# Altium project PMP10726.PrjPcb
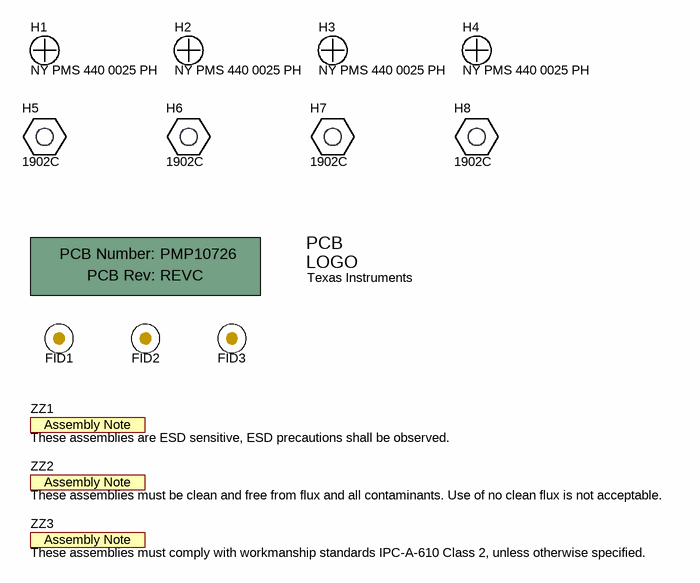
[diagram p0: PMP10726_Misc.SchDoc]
TID: PMP10726; TechSupport: http://www.ti.com/support; SCH_Rev: E3; PRJ_Title: 50W Buck-Boost; PRJ_Number: PMP10726; PRJ_Engineer: J Doong; PRJ_Customer: Public Release; PCB_Rev: REVC; PCB_Layout: J Doong; EVM_Orderable: N/A; CopyrightYear: 2016
2 sheets, 90 parts. Net scope: global (net labels, ports and power ports of the same name join across sheets).
Board file: PMP10726_TID.PcbDoc
Sheets:
  PMP10726_Misc.SchDoc
  PMP10726_Power.SchDoc

## Sheet PMP10726_Misc.SchDoc
size 431 x 279 mm; Date: Not shown in title block; ApprovedBy: Not shown in title block; CheckedBy: Not shown in title block; Author: Not shown in title block; CompanyName: Not shown in title block; Engineer: Not shown in title block; Organization: Not shown in title block; Address1: Not shown in title block; Address2: Not shown in title block; Address3: Not shown in title block; Address4: Not shown in title block; DocumentNumber: 2; Revision: Use project parameter SCH_Rev; SheetNumber: 2; SheetTotal: 2; PageSetup: Record=PageOptions¦CenterHorizontal=True¦CenterVertical=True¦PrintScale=1.00¦XCorrection=1.00¦YCorrection=1.00¦PrintKind=0¦BorderSize=5000000¦LeftOffset=0¦BottomOffset=0¦Orientation=2¦PaperLength=1000¦PaperWidth=1000¦Scale=100¦PaperSource=15¦PrintQuality=600¦MediaType=1¦DitherType=10¦PaperKind=Letter¦PrintScaleMode=1

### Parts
!PCB1  Printed Circuit Board  (value not drawn)  (mechanical)
FID1  Fiducial  [Fiducial10-20]  (value not drawn)
FID2  Fiducial  [Fiducial10-20]  (value not drawn)
FID3  Fiducial  [Fiducial10-20]  (value not drawn)
H1  NY PMS 440 0025 PH  [NY PMS 440 0025 PH]
H2  NY PMS 440 0025 PH  [NY PMS 440 0025 PH]
H3  NY PMS 440 0025 PH  [NY PMS 440 0025 PH]
H4  NY PMS 440 0025 PH  [NY PMS 440 0025 PH]
H5  1902C  [Keystone_1902C]
H6  1902C  [Keystone_1902C]
H7  1902C  [Keystone_1902C]
H8  1902C  [Keystone_1902C]
Logo1  Texas Instruments  [TI_Stacked_Overlay_Small]  (no BOM)
ZZ1  These assemblies are ESD sensitive, ESD precautions shall be observed.  [AssemblyNote]  (no BOM)
ZZ2  These assemblies must be clean and free from flux and all contaminants. Use of no clean flux is not acceptable.  [AssemblyNote]  (no BOM)
ZZ3  These assemblies must comply with workmanship standards IPC-A-610 Class 2, unless otherwise specified.  [AssemblyNote]  (no BOM)

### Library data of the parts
!PCB1 = PCB: Manufacturer: Any; PartNumber: PMP10726; SymbolCreator: a0412235
FID1-FID3 = Fiducial: Fiducial mark.  There is nothing to buy or mount.; SymbolCreator: codlsc
H1-H4 = NY PMS 440 0025 PH: Machine Screw, Round, #4-40 x 1/4, Nylon, Philips panhead; Manufacturer: B&F Fastener Supply; CompType: Hardware; SymbolCreator: codlsc; U/M: EA
H5-H8 = 1902C: Standoff, Hex, 0.5"L #4-40 Nylon; Manufacturer: Keystone; CompType: Hardware
Logo1 = TI_Logo: Texas Instrument Corporate Signature; SymbolCreator: codlsc
ZZ1-ZZ3 = AssemblyNote: SymbolCreator: codlsc

## Sheet PMP10726_Power.SchDoc
size 431 x 279 mm; Date: Not shown in title block; ApprovedBy: Not shown in title block; CheckedBy: Not shown in title block; Author: Not shown in title block; CompanyName: Not shown in title block; Engineer: Not shown in title block; Organization: Not shown in title block; Address1: Not shown in title block; Address2: Not shown in title block; Address3: Not shown in title block; Address4: Not shown in title block; DocumentNumber: 1; Revision: Use project parameter SCH_Rev; SheetNumber: 1; SheetTotal: 2; PageSetup: Record=PageOptions¦CenterHorizontal=True¦CenterVertical=True¦PrintScale=1.00¦XCorrection=1.00¦YCorrection=1.00¦PrintKind=0¦BorderSize=5000000¦LeftOffset=0¦BottomOffset=0¦Orientation=2¦PaperLength=1000¦PaperWidth=1000¦Scale=100¦PaperSource=15¦PrintQuality=600¦MediaType=1¦DitherType=10¦PaperKind=Letter¦PrintScaleMode=1
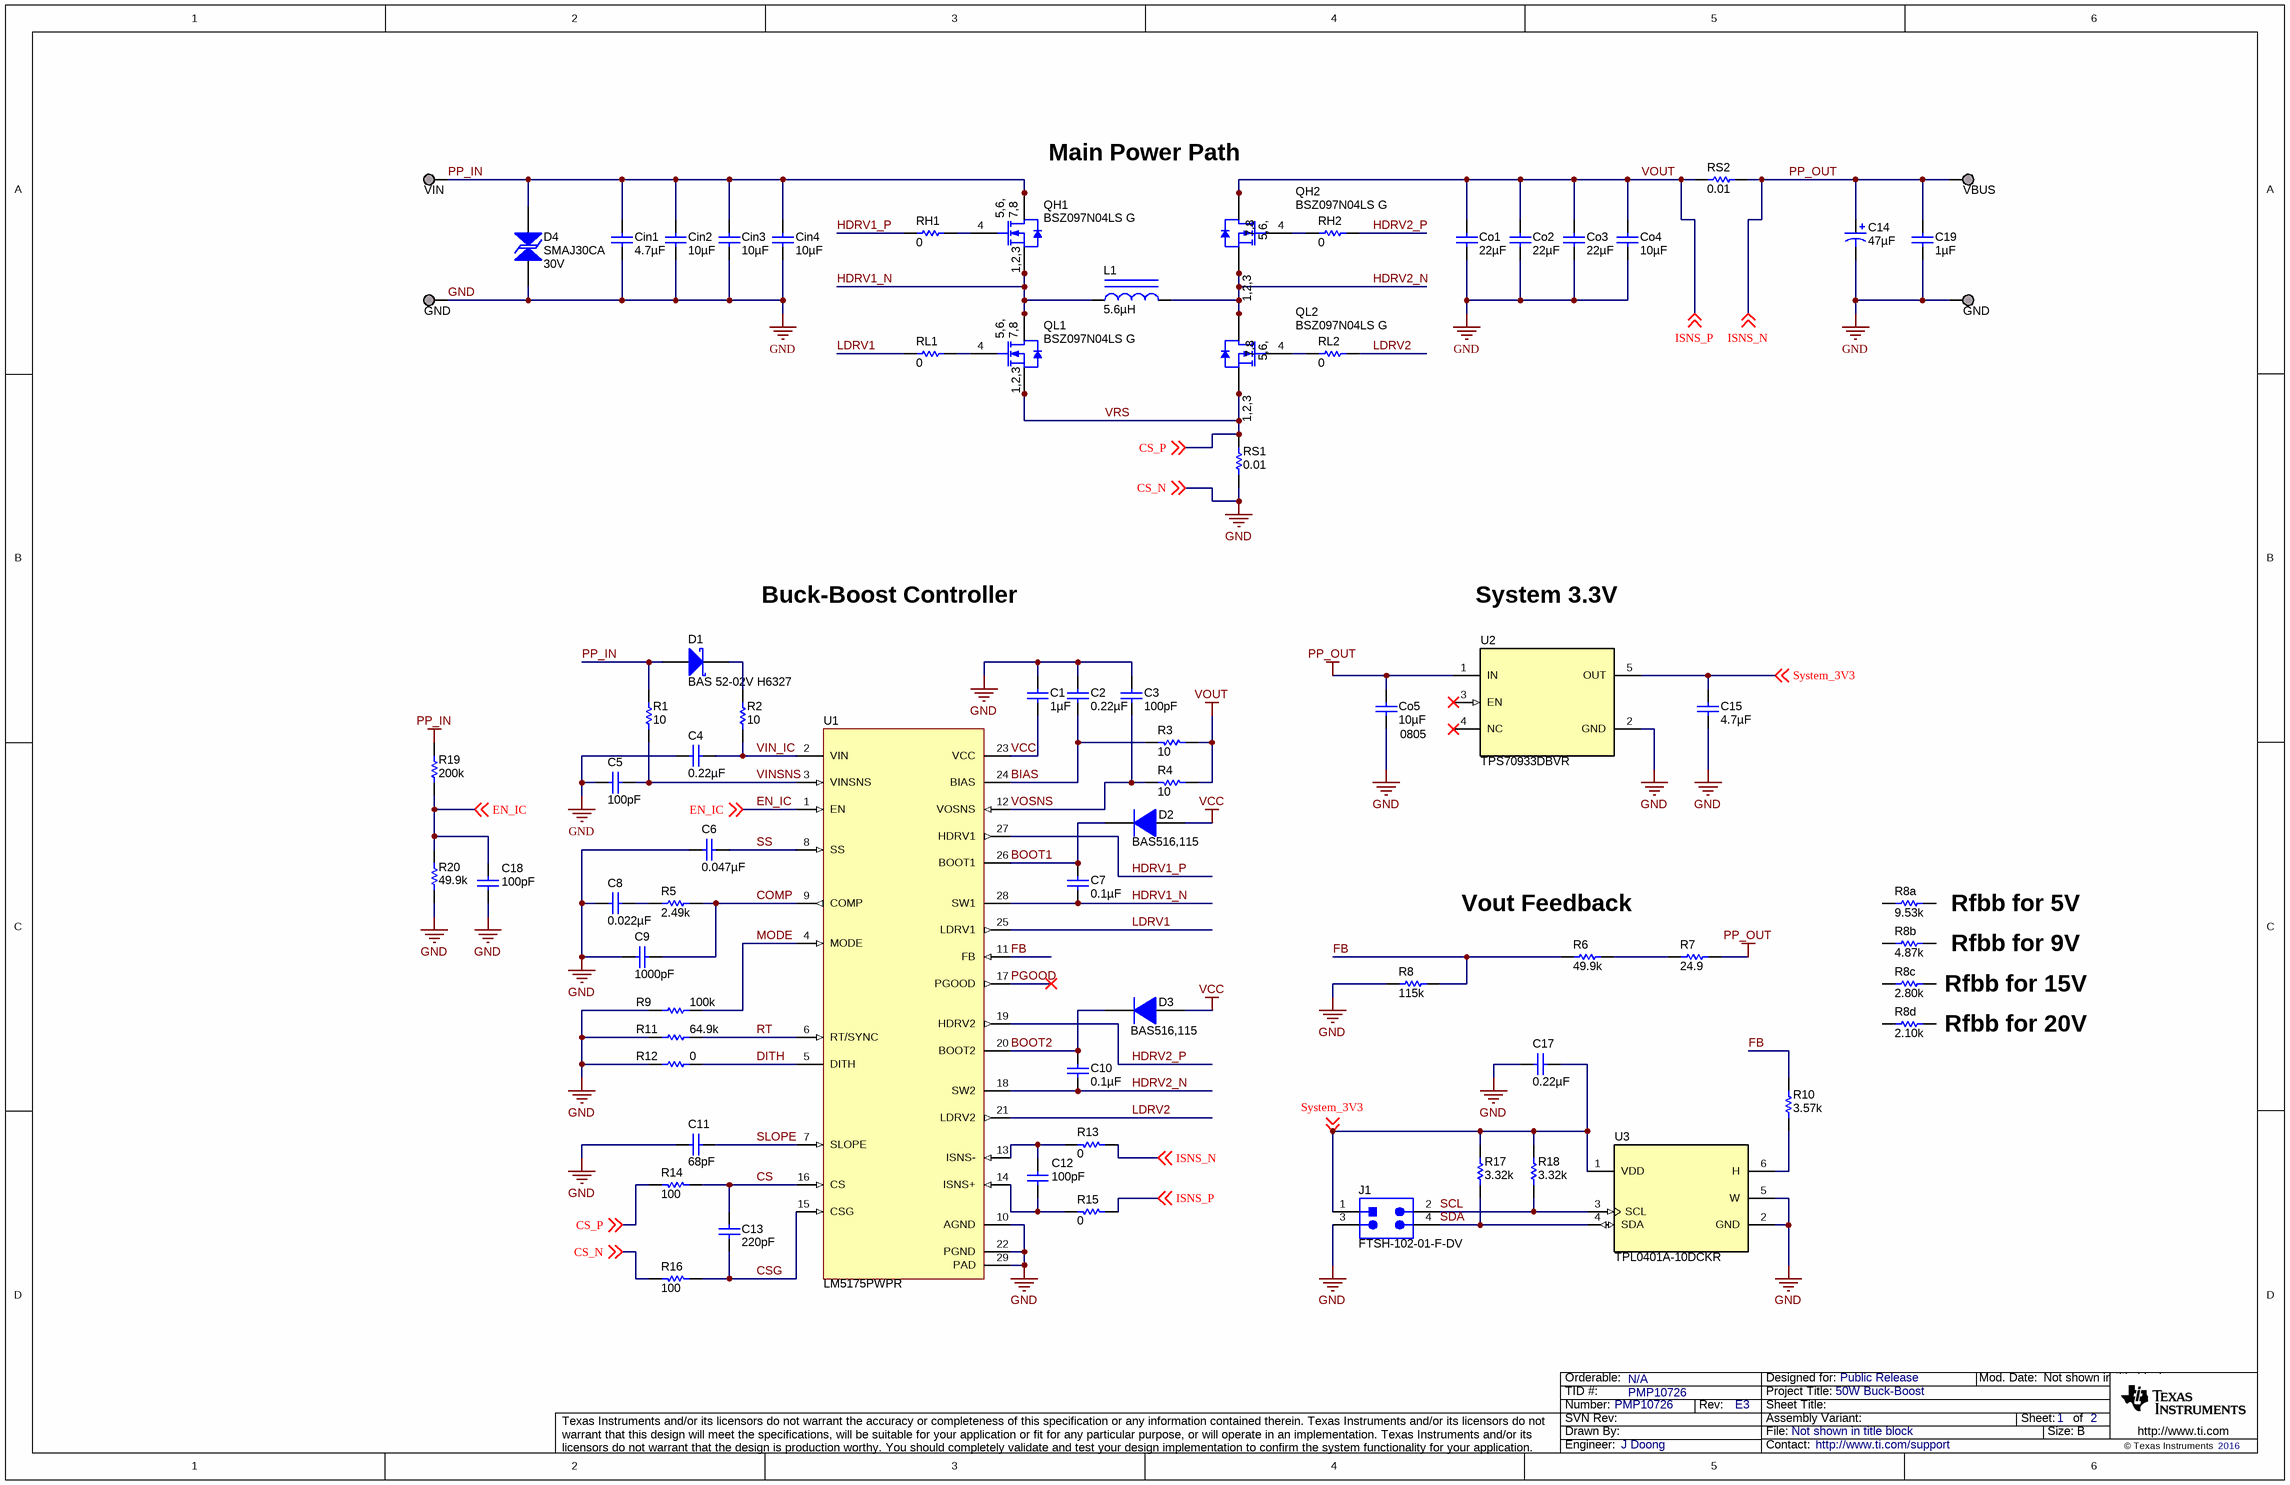
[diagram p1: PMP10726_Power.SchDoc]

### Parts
C1  ValueDisplayed: 1µF  [0603L]  (hidden comment: GRM188R71E105KA12D)
C2  ValueDisplayed: 0.22µF  [0402L]  (hidden comment: C1005X7R1C224K050BC)
C3  ValueDisplayed: 100pF  [0402L]  (hidden comment: GRM1535C1H101JDD5D)
C4  ValueDisplayed: 0.22µF  [0603L]  (hidden comment: C1608X7R1H224K080AB)
C5  ValueDisplayed: 100pF  [0402L]  (hidden comment: GRM1535C1H101JDD5D)
C6  ValueDisplayed: 0.047µF  [0402]  (hidden comment: C1005X7R1H473K050BB)
C7  ValueDisplayed: 0.1µF  [0603_HV]  (hidden comment: GCM188R71H104KA57D)
C8  ValueDisplayed: 0.022µF  [0402L]  (hidden comment: GCM155R71H223KA55D)
C9  ValueDisplayed: 1000pF  [0402]  (hidden comment: 885012205061)
C10  ValueDisplayed: 0.1µF  [0603_HV]  (hidden comment: GCM188R71H104KA57D)
C11  ValueDisplayed: 68pF  [0402L]  (hidden comment: GRM1555C1H680JA01D)
C12  ValueDisplayed: 100pF  [0402L]  (hidden comment: GRM1535C1H101JDD5D)
C13  ValueDisplayed: 220pF  [0402L]  (hidden comment: GRM1555C1H221JA01D)
C14  ValueDisplayed: 47µF  [SM_RADIAL_6.3AMM]  (hidden comment: UUD1E470MCL1GS)
C15  ValueDisplayed: 4.7µF  [0805L]  (hidden comment: GRM21BR71C475KA73L)
C17  ValueDisplayed: 0.22µF  [0402L]  (hidden comment: C1005X7R1C224K050BC)
C18  ValueDisplayed: 100pF  [0402L]  (hidden comment: GRM1535C1H101JDD5D)
C19  ValueDisplayed: 1µF  [0603L]  (hidden comment: GRM188R71E105KA12D)
Cin1  ValueDisplayed: 4.7µF  [1206L]  (hidden comment: GRM31CR71H475KA12L)
Cin2  ValueDisplayed: 10µF  [1210L]  (hidden comment: GRM32ER71H106KA12L)
Cin3  ValueDisplayed: 10µF  [1210L]  (hidden comment: GRM32ER71H106KA12L)
Cin4  ValueDisplayed: 10µF  [1210L]  (hidden comment: GRM32ER71H106KA12L)
Co1  ValueDisplayed: 22µF  [1210L]  (hidden comment: GRM32ER71E226KE15L)
Co2  ValueDisplayed: 22µF  [1210L]  (hidden comment: GRM32ER71E226KE15L)
Co3  ValueDisplayed: 22µF  [1210L]  (hidden comment: GRM32ER71E226KE15L)
Co4  ValueDisplayed: 10µF  [1206L]  (hidden comment: C3216X7R1E106M160AE)
Co5  ValueDisplayed: 10µF  Cap_Case: 0805  [0805L]  (hidden comment: EMK212BB7106MG-T)
D1  BAS 52-02V H6327  [SOD-523]
D2  BAS516,115  [SOD-523]
D3  BAS516,115  [SOD-523]
D4  SMAJ30CA  value 30V  [SMA]
J1  FTSH-102-01-F-DV  [Samtec_FTSH-102-01-x-DV]
L1  ValueDisplayed: 5.6µH  [XAL5050]  (hidden comment: XAL5050-562MEB)
QH1  BSZ097N04LS G  [PG-TSDSON-8]
QH2  BSZ097N04LS G  [PG-TSDSON-8]
QL1  BSZ097N04LS G  [PG-TSDSON-8]
QL2  BSZ097N04LS G  [PG-TSDSON-8]
R1  ValueDisplayed: 10  [0402L]  (hidden comment: CRCW040210R0JNED)
R2  ValueDisplayed: 10  [0402L]  (hidden comment: CRCW040210R0JNED)
R3  ValueDisplayed: 10  [0402L]  (hidden comment: CRCW040210R0JNED)
R4  ValueDisplayed: 10  [0402L]  (hidden comment: CRCW040210R0JNED)
R5  ValueDisplayed: 2.49k  [0402]  (hidden comment: CRCW04022K49FKED)
R6  ValueDisplayed: 49.9k  [0402L]  (hidden comment: CRCW040249K9FKED)
R7  ValueDisplayed: 24.9  [0603L]  (hidden comment: CRCW060324R9FKEA)
R8  ValueDisplayed: 115k  [0402L]  (hidden comment: CRCW0402115KFKED)
R8a  ValueDisplayed: 9.53k  [0402L]  (hidden comment: CRCW04029K53FKED)
R8b  ValueDisplayed: 4.87k  [0402]  (hidden comment: CRCW04024K87FKED)
R8c  ValueDisplayed: 2.80k  [0402]  (hidden comment: CRCW04022K80FKED)
R8d  ValueDisplayed: 2.10k  [0402]  (hidden comment: CRCW04022K10FKED)
R9  ValueDisplayed: 100k  [0402L]  (hidden comment: CRCW0402100KFKED)
R10  ValueDisplayed: 3.57k  [0402L]  (hidden comment: CRCW04023K57FKED)
R11  ValueDisplayed: 64.9k  [0402L]  (hidden comment: CRCW040264K9FKED)
R12  ValueDisplayed: 0  [0402L]  (hidden comment: CRCW04020000Z0ED)
R13  ValueDisplayed: 0  [0402L]  (hidden comment: CRCW04020000Z0ED)
R14  ValueDisplayed: 100  [0402L]  (hidden comment: CRCW0402100RFKED)
R15  ValueDisplayed: 0  [0402L]  (hidden comment: CRCW04020000Z0ED)
R16  ValueDisplayed: 100  [0402L]  (hidden comment: CRCW0402100RFKED)
R17  ValueDisplayed: 3.32k  [0402L]  (hidden comment: CRCW04023K32FKED)
R18  ValueDisplayed: 3.32k  [0402L]  (hidden comment: CRCW04023K32FKED)
R19  ValueDisplayed: 200k  [0402L]  (hidden comment: CRCW0402200KFKED)
R20  ValueDisplayed: 49.9k  [0402L]  (hidden comment: CRCW040249K9FKED)
RH1  ValueDisplayed: 0  [0402L]  (hidden comment: CRCW04020000Z0ED)
RH2  ValueDisplayed: 0  [0402L]  (hidden comment: CRCW04020000Z0ED)
RL1  ValueDisplayed: 0  [0402L]  (hidden comment: CRCW04020000Z0ED)
RL2  ValueDisplayed: 0  [0402L]  (hidden comment: CRCW04020000Z0ED)
RS1  ValueDisplayed: 0.01  [1206L]  (hidden comment: WSLP1206R0100FEA)
RS2  ValueDisplayed: 0.01  [1206]  (hidden comment: WSLP1206R0100FEA)
TP1  VBUS  [Keystone_5019]
TP2  VIN  [Keystone_5019]
TP3  GND  [Keystone_5019]
TP4  GND  [Keystone_5019]
U1  LM5175PWPR  [PWP0028F_N]
U2  TPS70933DBVR  [DBV0005A_L]
U3  TPL0401A-10DCKR  [DCK0006A_N]

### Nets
GND: C1.2 C2.1 C3.1 C4.1 C5.1 C6.2 C8.1 C9.2 C11.2 C14.2(-) C15.1 C17.1 C18.2 C19.1 Cin1.2 Cin2.2 Cin3.2 Cin4.2 Co1.2 Co2.2 Co3.2 Co4.2 Co5.2 D4.2 J1.3 R8.2 R9.2 R11.2 R12.2 R16.2 R20.2 RS1.1 TP3.1 TP4.1 U1.10(AGND) U1.22(PGND) U1.29(PAD) U2.2(GND) U3.2(GND) U3.5(W) ; off-sheet CS_N  [also labelled CS_N]
PP_IN: Cin1.1 Cin2.1 Cin3.1 Cin4.1 D1.2(A) D4.1 QH1.5(D) QH1.6(D) QH1.7(D) QH1.8(D) QH1.9(D) R1.2 R19.1 TP2.1
PP_OUT: C14.1(+) C19.2 Co5.1 R7.2 R13.1 RS2.2 TP1.1 U2.1(IN) ; off-sheet ISNS_N  [also labelled ISNS_N]
VCC: C1.1 D2.2(A) D3.2(A) U1.23(VCC)
VOUT: Co1.1 Co2.1 Co3.1 Co4.1 QH2.5(D) QH2.6(D) QH2.7(D) QH2.8(D) QH2.9(D) R3.2 R4.2 R15.1 RS2.1 ; off-sheet ISNS_P  [also labelled ISNS_P]
BIAS: C2.2 R3.1 U1.24(BIAS)
BOOT1: C7.1 D2.1(K) U1.26(BOOT1)
BOOT2: C10.1 D3.1(K) U1.20(BOOT2)
COMP: C9.1 R5.2 U1.9(COMP)
CS: C13.1 R14.1 U1.16(CS)
CSG: C13.2 R16.1 U1.15(CSG)
DITH: R12.1 U1.5(DITH)
EN_IC: C18.1 R19.2 R20.1 U1.1(EN) ; off-sheet EN_IC
FB: R6.2 R8.1 R10.1 U1.11(FB)
HDRV1_N: C7.2 L1.1 QH1.1(S) QH1.2(S) QH1.3(S) QL1.5(D) QL1.6(D) QL1.7(D) QL1.8(D) QL1.9(D) U1.28(SW1)
HDRV1_P: RH1.1 U1.27(HDRV1)
HDRV2_N: C10.2 L1.2 QH2.1(S) QH2.2(S) QH2.3(S) QL2.5(D) QL2.6(D) QL2.7(D) QL2.8(D) QL2.9(D) U1.18(SW2)
HDRV2_P: RH2.2 U1.19(HDRV2)
LDRV1: RL1.1 U1.25(LDRV1)
LDRV2: RL2.2 U1.21(LDRV2)
MODE: R9.1 U1.4(MODE)
PGOOD: U1.17(PGOOD)
RT: R11.1 U1.6(RT/SYNC)
SCL: J1.2 R18.1 U3.3(SCL)
SDA: J1.4 R17.1 U3.4(SDA)
SLOPE: C11.1 U1.7(SLOPE)
SS: C6.1 U1.8(SS)
System_3V3: C15.2 C17.2 J1.1 R17.2 R18.2 U2.5(OUT) U3.1(VDD) ; off-sheet System_3V3
VIN_IC: C4.2 R2.1 U1.2(VIN)
VINSNS: C5.2 R1.1 U1.3(VINSNS)
VOSNS: C3.2 R4.1 U1.12(VOSNS)
VRS: QL1.1(S) QL1.2(S) QL1.3(S) QL2.1(S) QL2.2(S) QL2.3(S) R14.2 RS1.2 ; off-sheet CS_P  [also labelled CS_P]
NetC8_2: C8.2 R5.1
NetC12_1: C12.1 R13.2 U1.13(ISNS-)
NetC12_2: C12.2 R15.2 U1.14(ISNS+)
NetD1_1: D1.1(K) R2.2
NetQH1_4: QH1.4(G) RH1.2
NetQH2_4: QH2.4(G) RH2.1
NetQL1_4: QL1.4(G) RL1.2
NetQL2_4: QL2.4(G) RL2.1
NetR6_1: R6.1 R7.1
NetR10_2: R10.2 U3.6(H)

Not connected (* = marked no-connect by the designer): R8a 1 2; R8b 1 2; R8c 1 2; R8d 1 2; U2 3(EN)* 4(NC)*

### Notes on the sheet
- Main Power Path
- Buck-Boost Controller
- System 3.3V
- (near R6) Vout Feedback
- Rfbb for 5V
- Rfbb for 9V
- Rfbb for 15V
- Rfbb for 20V

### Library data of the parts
C1 C19 = GRM188R71E105KA12D: CAP, CERM, 1 µF, 25 V, +/- 10%, X7R, 0603; Manufacturer: MuRata; Polarized: N; CompType: Capacitor; Value: 1uF; U/M: EA; Cap_F: 0.000001; Tolerance_%: 10; Value1: Unknown; VDC_V: 25; Value2: 25V; TaMin_C: -55; TaMax_C: 125; Cap_Case: 0603
C2 C17 = C1005X7R1C224K050BC: CAP, CERM, 0.22 µF, 16 V, +/- 10%, X7R, 0402; Manufacturer: TDK; Polarized: N; CompType: Capacitor; Value: 0.22uF; U/M: EA; Cap_F: 0.00000022; Tolerance_%: 10; Value1: Unknown; VDC_V: 16; Value2: 16V; TaMin_C: -55; TaMax_C: 125; Cap_Case: 0402; AEC Category: Q200
C3 C5 C12 C18 = GRM1535C1H101JDD5D: CAP, CERM, 100 pF, 50 V, +/- 5%, C0G/NP0, 0402; Manufacturer: MuRata; Polarized: N; CompType: Capacitor; Value: 100pF; U/M: EA; Cap_F: 0.0000000001; Tolerance_%: 5; Value1: Unknown; VDC_V: 50; Value2: 50V; TaMin_C: -55; TaMax_C: 125; Cap_Case: 0402; AEC Category: Q200
C4 = C1608X7R1H224K080AB: CAP, CERM, 0.22uF, 50V, +/-10%, X7R, 0603; Manufacturer: TDK; Polarized: N; CompType: Capacitor; U/M: EA; Cap_F: 0.00000022; Tolerance_%: 10; Value1: Unknown; VDC_V: 50; TaMin_C: -55; TaMax_C: 125; Cap_Case: 0603
C6 = C1005X7R1H473K050BB: CAP, CERM, 0.047 µF, 50 V, +/- 10%, X7R, 0402; Manufacturer: TDK; Polarized: N; CompType: Capacitor; Value: 0.047uF; U/M: EA; Cap_F: 0.000000047; Tolerance_%: 10; ESR_ohm: 0.06407; Value1: 0.06407 ohm; VDC_V: 50; Value2: 50V; IRMS_A: 0.646122; TaMin_C: -55; TaMax_C: 125; SizeArea_mm2: 0.5; SizeAreaWB_mm2: 3; SizeX_mm: 1; SizeZ_mm: 0.6; AEC Category: Q200
C7 C10 = GCM188R71H104KA57D: CAP, CERM, 0.1 µF, 50 V, +/- 10%, X7R, 0603; Manufacturer: MuRata; Polarized: N; CompType: Capacitor; Value: 0.1uF; U/M: EA; Cap_F: 0.0000001; Tolerance_%: 10; ESR_ohm: 0.02; Value1: 0.02 ohm; VDC_V: 50; Value2: 50V; IRMS_A: 1.84; TaMin_C: -55; TaMax_C: 125; Cap_Case: 0603
C8 = GCM155R71H223KA55D: CAP, CERM, 0.022 µF, 50 V, +/- 10%, C0G/NP0, 0402; Manufacturer: MuRata; Polarized: N; CompType: Capacitor; Value: 0.022uF; U/M: EA; Cap_F: 0.000000022; Tolerance_%: 10; Value1: Unknown; VDC_V: 50; Value2: 50V; TaMin_C: -55; TaMax_C: 125; Cap_Case: 0402; AEC Category: Q200
C9 = 885012205061: CAP, CERM, 1000 pF, 50 V, +/- 10%, X7R, 0402; Manufacturer: Wurth Elektronik; Polarized: N; CompType: Capacitor; Value: 1000pF; U/M: EA; Cap_F: 0.000000001; Tolerance_%: 10; Value1: Unknown; VDC_V: 50; Value2: 50V; TaMin_C: -55; TaMax_C: 125; SizeArea_mm2: 0.5; SizeAreaWB_mm2: 3; SizeX_mm: 1; SizeZ_mm: 0.6; AEC Category: Q200
C11 = GRM1555C1H680JA01D: CAP, CERM, 68 pF, 50 V, +/- 5%, C0G/NP0, 0402; Manufacturer: MuRata; Polarized: N; CompType: Capacitor; Value: 68pF; U/M: EA; Cap_F: 0.000000000068; Tolerance_%: 5; Value1: Unknown; VDC_V: 50; Value2: 50V; TaMin_C: -55; TaMax_C: 125; Cap_Case: 0402; AEC Category: Q200
C13 = GRM1555C1H221JA01D: CAP, CERM, 220 pF, 50 V, +/- 5%, C0G/NP0, 0402; Manufacturer: MuRata; Polarized: N; CompType: Capacitor; Value: 220pF; U/M: EA; Cap_F: 0.00000000022; Tolerance_%: 5; Value1: Unknown; VDC_V: 50; Value2: 50V; TaMin_C: -55; TaMax_C: 125; Cap_Case: 0402; AEC Category: Q200
C14 = UUD1E470MCL1GS: CAP, AL, 47 µF, 25 V, +/- 20%, 0.44 ohm, SMD; Manufacturer: Nichicon; Polarized: Y; CompType: Capacitor; Value: 47uF; U/M: EA; Cap_F: 0.000047; Tolerance_%: 20; VDC_V: 25; Value2: 25V; ESR_ohm: 0.44; IRMS_A: 0.23; TaMin_C: -55; TaMax_C: 105; Cap_Case: 6.3x5.8; AEC Category: Q200
C15 = GRM21BR71C475KA73L: CAP, CERM, 4.7 µF, 16 V, +/- 10%, X7R, 0805; Manufacturer: MuRata; Polarized: N; CompType: Capacitor; Value: 4.7uF; U/M: EA; Cap_F: 0.0000047; Tolerance_%: 10; ESR_ohm: 0.006; Value1: 0.006 ohm; VDC_V: 16; Value2: 16V; TaMin_C: -55; TaMax_C: 125; Cap_Case: 0805; AEC Category: Q200
Cin1 = GRM31CR71H475KA12L: CAP, CERM, 4.7 µF, 50 V, +/- 10%, X7R, 1206; Manufacturer: MuRata; Polarized: N; CompType: Capacitor; Value: 4.7uF; U/M: EA; Cap_F: 0.0000047; Tolerance_%: 10; Value1: Unknown; VDC_V: 50; Value2: 50V; TaMin_C: -55; TaMax_C: 125; Cap_Case: 2220
Cin2-Cin4 = GRM32ER71H106KA12L: CAP, CERM, 10 µF, 50 V, +/- 10%, X7R, 1210; Manufacturer: MuRata; Polarized: N; CompType: Capacitor; Value: 10uF; U/M: EA; Cap_F: 0.00001; Tolerance_%: 10; Value1: Unknown; VDC_V: 50; Value2: 50V; TaMin_C: -55; TaMax_C: 125; Cap_Case: 1210; AEC Category: Q200
Co1-Co3 = GRM32ER71E226KE15L: CAP, CERM, 22 µF, 25 V, +/- 10%, X7R, 1210; Manufacturer: MuRata; Polarized: N; CompType: Capacitor; Value: 22uF; U/M: EA; Cap_F: 0.000022; Tolerance_%: 10; Value1: Unknown; VDC_V: 25; Value2: 25V; TaMin_C: -55; TaMax_C: 125; Cap_Case: 1210; AEC Category: Q200
Co4 = C3216X7R1E106M160AE: CAP, CERM, 10 µF, 25 V, +/- 20%, X7R, 1206_190; Manufacturer: TDK; Polarized: N; CompType: Capacitor; Value: 10uF; U/M: EA; Cap_F: 0.00001; Tolerance_%: 20; Value1: Unknown; VDC_V: 25; Value2: 25V; TaMin_C: -55; TaMax_C: 125; Cap_Case: 1206; AEC Category: Q200
Co5 = EMK212BB7106MG-T: CAP, CERM, 10 µF, 16 V, +/- 20%, X7R, 0805; Manufacturer: Taiyo Yuden; Polarized: N; CompType: Capacitor; Value: 10uF; U/M: EA; Cap_F: 0.00001; Tolerance_%: 20; Value1: Unknown; VDC_V: 16; Value2: 16V; TaMin_C: -55; TaMax_C: 125; AEC Category: Q200
D1 = BAS 52-02V H6327: Diode, Schottky, 45 V, 0.75 A, SOD-523; Manufacturer: Infineon Technologies; Value: 45V; U/M: EA; Vf_V: 0.6; Value1: 0.75A; Value2: 0.6V; Io_A: 0.75; Vr_V: 45; TJmax_C: 150
D2 D3 = BAS516,115: Diode, Switching, 100V, 0.25A, SOD-523; Manufacturer: NXP Semiconductor; U/M: EA; Vf_V: 1.25; Value2: 1.25V; Io_A: 0.25; Vr_V: 100; TJmax_C: 150
D4 = SMAJ30CA: Diode, TVS, Bi, 30 V, 400 W, SMA; Manufacturer: Littelfuse; U/M: EA; Power_W: 400; Vr_V: 30; Value1: 400W; RJA_CperW: 120; AEC Category: Q101
J1 = FTSH-102-01-F-DV: Header, 1.27mm, 2x2, Gold, SMT; Manufacturer: Samtec; SymbolCreator: a0412235; U/M: EA
L1 = XAL5050-562MEB: Inductor, Shielded, Composite, 5.6 µH, 6.3 A, 0.03 ohm, SMD; Manufacturer: Coilcraft; Value: 5.6uH; Ind_H: 5.6E-6; Imax_A: 6.3; Irms: 7.2A @ 40C rise; Isat: 6.3A @ 30% inductance drop; DCR_ohm: 0.03; Value2: 6.3A
QH1 QH2 QL1 QL2 = BSZ097N04LS G: MOSFET, N-CH, 40 V, 40 A, PG-TSDSON-8; Manufacturer: Infineon Technologies; Alternate Manufacturer: None; U/M: EA; ChType: N; Value: 40V; VdsMax_V: 40; Value1: 0.0142 ohm; Rdson45_ohm: 0.0142; Value2: 8.6 nC; QgTyp_nC: 8.6; Vgs_V: 20; SizeAreaWB_mm2: 19.36; SizeArea_mm2: 11.56; SizeX_mm: 3.4; SizeZ_mm: 1.1; AEC Category: Q101
R1-R4 = CRCW040210R0JNED: RES, 10, 5%, 0.063 W, 0402; Manufacturer: Vishay-Dale; CompType: Resistor; Value: 10; Value_Code: 10R0; Tolerance_%: 5; Power_W: 0.063; Value2: 0.063W; VDC_V: 50; TempCo: 200 ppm/C; EIA_Code: E24; U/M: EA; AEC Category: Q200
R5 = CRCW04022K49FKED: RES, 2.49 k, 1%, 0.063 W, 0402; Manufacturer: Vishay-Dale; CompType: Resistor; Value: 2.49k; Res_ohm: 2490; Value_Code: 2k49; Tolerance_%: 1; Power_W: 0.063; Value2: 0.063W; VDC_V: 50; TempCo: 100 ppm/C; SizeArea_mm2: 0.5; SizeZ_mm: 0.6; EIA_Code: E96; U/M: EA; AEC Category: Q200
R6 R20 = CRCW040249K9FKED: RES, 49.9 k, 1%, 0.063 W, 0402; Manufacturer: Vishay-Dale; CompType: Resistor; Value: 49.9k; Res_ohm: 49900; Value_Code: 49k9; Tolerance_%: 1; Power_W: 0.063; Value2: 0.063W; VDC_V: 50; TempCo: 100 ppm/C; EIA_Code: E96; U/M: EA; AEC Category: Q200
R7 = CRCW060324R9FKEA: RES, 24.9, 1%, 0.1 W, 0603; Manufacturer: Vishay-Dale; CompType: Resistor; Value: 24.9; Value_Code: 24R9; Tolerance_%: 1; Power_W: 0.1; Value2: 0.1W; VDC_V: 75; TempCo: 100 ppm/C; EIA_Code: E96; U/M: EA
R8 = CRCW0402115KFKED: RES, 115 k, 1%, 0.063 W, 0402; Manufacturer: Vishay-Dale; CompType: Resistor; Value: 115k; Res_ohm: 115000; Tolerance_%: 1; Power_W: 0.063; Value2: 0.063W; VDC_V: 50; TempCo: 100 ppm/C; EIA_Code: E96; U/M: EA; AEC Category: Q200
R8a = CRCW04029K53FKED: RES, 9.53 k, 1%, 0.063 W, 0402; Manufacturer: Vishay-Dale; CompType: Resistor; Value: 9.53k; Res_ohm: 9530; Value_Code: 9k53; Tolerance_%: 1; Power_W: 0.063; Value2: 0.063W; VDC_V: 50; TempCo: 100 ppm/C; EIA_Code: E96; U/M: EA; AEC Category: Q200
R8b = CRCW04024K87FKED: RES, 4.87 k, 1%, 0.063 W, 0402; Manufacturer: Vishay-Dale; CompType: Resistor; Value: 4.87k; Res_ohm: 4870; Value_Code: 4k87; Tolerance_%: 1; Power_W: 0.063; Value2: 0.063W; VDC_V: 50; TempCo: 100 ppm/C; SizeArea_mm2: 0.5; SizeZ_mm: 0.6; EIA_Code: E96; U/M: EA; AEC Category: Q200
R8c = CRCW04022K80FKED: RES, 2.80 k, 1%, 0.063 W, 0402; Manufacturer: Vishay-Dale; CompType: Resistor; Value: 2.80k; Res_ohm: 2800; Value_Code: 2k80; Tolerance_%: 1; Power_W: 0.063; Value2: 0.063W; VDC_V: 50; TempCo: 100 ppm/C; SizeArea_mm2: 0.5; SizeZ_mm: 0.6; EIA_Code: E96; U/M: EA; AEC Category: Q200
R8d = CRCW04022K10FKED: RES, 2.10 k, 1%, 0.063 W, 0402; Manufacturer: Vishay-Dale; CompType: Resistor; Value: 2.10k; Res_ohm: 2100; Value_Code: 2k10; Tolerance_%: 1; Power_W: 0.063; Value2: 0.063W; VDC_V: 50; TempCo: 100 ppm/C; SizeArea_mm2: 0.5; SizeZ_mm: 0.6; EIA_Code: E96; U/M: EA; AEC Category: Q200
R9 = CRCW0402100KFKED: RES, 100 k, 1%, 0.063 W, 0402; Manufacturer: Vishay-Dale; CompType: Resistor; Value: 100k; Res_ohm: 100000; Tolerance_%: 1; Power_W: 0.063; Value2: 0.063W; VDC_V: 50; TempCo: 100 ppm/C; EIA_Code: E96; U/M: EA; AEC Category: Q200
R10 = CRCW04023K57FKED: RES, 3.57 k, 1%, 0.063 W, 0402; Manufacturer: Vishay-Dale; CompType: Resistor; Value: 3.57k; Res_ohm: 3570; Value_Code: 3k57; Tolerance_%: 1; Power_W: 0.063; Value2: 0.063W; VDC_V: 50; TempCo: 100 ppm/C; EIA_Code: E96; U/M: EA; AEC Category: Q200
R11 = CRCW040264K9FKED: RES, 64.9 k, 1%, 0.063 W, 0402; Manufacturer: Vishay-Dale; CompType: Resistor; Value: 64.9k; Res_ohm: 64900; Value_Code: 64k9; Tolerance_%: 1; Power_W: 0.063; Value2: 0.063W; VDC_V: 50; TempCo: 100 ppm/C; EIA_Code: E96; U/M: EA; AEC Category: Q200
R12 = CRCW04020000Z0ED: RES, 0, 5%, 0.063 W, 0402; Manufacturer: Vishay-Dale; CompType: Resistor; Value: 0; Tolerance_%: 5; Value2: 0.063W; VDC_V: 50; TempCo: 200 ppm/C; U/M: EA; Value_Code: 0000; Power_W: 0.063; EIA_Code: E24; AEC Category: Q200
R13 R15 RH1 RH2 RL1 RL2 = CRCW04020000Z0ED: RES, 0, 5%, 0.063 W, 0402; Manufacturer: Vishay-Dale; CompType: Resistor; Value: 0; Value_Code: 0000; Tolerance_%: 5; Power_W: 0.063; Value2: 0.063W; VDC_V: 50; TempCo: 200 ppm/C; EIA_Code: E24; U/M: EA; AEC Category: Q200
R14 R16 = CRCW0402100RFKED: RES, 100, 1%, 0.063 W, 0402; Manufacturer: Vishay-Dale; CompType: Resistor; Value: 100; Value_Code: 100R; Tolerance_%: 1; Power_W: 0.063; Value2: 0.063W; VDC_V: 50; TempCo: 100 ppm/C; EIA_Code: E96; U/M: EA; AEC Category: Q200
R17 R18 = CRCW04023K32FKED: RES, 3.32 k, 1%, 0.063 W, 0402; Manufacturer: Vishay-Dale; CompType: Resistor; Value: 3.32k; Res_ohm: 3320; Value_Code: 3k32; Tolerance_%: 1; Power_W: 0.063; Value2: 0.063W; VDC_V: 50; TempCo: 100 ppm/C; EIA_Code: E96; U/M: EA; AEC Category: Q200
R19 = CRCW0402200KFKED: RES, 200 k, 1%, 0.063 W, 0402; Manufacturer: Vishay-Dale; CompType: Resistor; Value: 200k; Res_ohm: 200000; Tolerance_%: 1; Power_W: 0.063; Value2: 0.063W; VDC_V: 50; TempCo: 100 ppm/C; EIA_Code: E96; U/M: EA; AEC Category: Q200
RS1 RS2 = WSLP1206R0100FEA: RES, 0.01, 1%, 1 W, 1206; Manufacturer: Vishay-Dale; CompType: Resistor; Value: 0.01; Tolerance_%: 1; TempCo: 75 ppm/C; U/M: EA; Value_Code: R010; Value2: 1W; EIA_Code: E96; AEC Category: Q200
TP1-TP4 = 5019: Test Point, Miniature, SMT; Manufacturer: Keystone; CompType: Test Point Loop; U/M: EA
U1 = LM5175PWPR: 42V Wide VIN 4-Switch Synchronous Buck-Boost Controller, PWP0028F; Alternate PartNumber: LM5175PWPT; Manufacturer: Texas Instruments; SymbolCreator: a0411947; CompType: IC; U/M: EA
U2 = TPS70933DBVR: 150-mA, 30-V, 1-uA IQ Voltage Regulator with Enable, DBV0005A; Alternate PartNumber: TPS70933DBVT; Manufacturer: Texas Instruments; SymbolCreator: Altium; SizeArea_mm2: 8.12; SizeAreaWB_mm2: 14.82; SizeX_mm: 2.8; SizeY_mm: 2.9; SizeZ_mm: 1.45; CompType: IC; U/M: EA
U3 = TPL0401A-10DCKR: 128 TAPS Single Channel Digital Potentiometer with I2C Interface, DCK0006A; Manufacturer: Texas Instruments; SymbolCreator: Altium; CompType: IC; U/M: EA

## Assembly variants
001: not fitted C12 FID1 FID2 FID3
